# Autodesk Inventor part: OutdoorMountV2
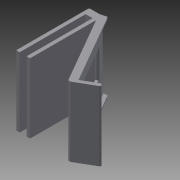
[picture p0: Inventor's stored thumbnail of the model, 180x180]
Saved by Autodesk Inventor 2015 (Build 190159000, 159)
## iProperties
Created: 2017-04
Part Number: OutdoorMountV2
Material: Generisch
Document SubType Name: Modeling
Designer: Andreas
Density: 1 g/cm^3
Appearance: Vorgabe
Author: Andreas
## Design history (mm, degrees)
sketch "Skizze1"
  geometry: L1 (0, 0)-(0, 105); L2 (0, 105)-(20, 105); L3 (0, 0)-(5, 0); L4 (5, 0)-(5, 95); L5 (5, 95)-(15, 95); L6 (15, 95)-(15, 0); L7 (15, 0)-(20, 0); L8 (20, 0)-(20, 95); L9 (25, 105)-(143.136, 105); L10 (20, 95)-(73.912, 1.622); L11 (20, 95)-(127.824, 95); L12 (20, 105)-(141.313, 105); L13 (20, 105)-(77.5, 5.407); L14 (20, 105)-(135, 105); L15 (77.5, 5.407)-(103.481, 20.407); L16 (103.481, 20.407)-(105.981, 16.077); L17 (105.981, 16.077)-(78.135, 0); L18 (78.135, 0)-(74.848, 0); L19 (74.848, 0)-(73.912, 1.622)
  constraints: 38 end point, 8 horizontal, 6 perpendicular, 2 equal length, 2 vertical, 1 parallel, 1 point on line
  dimensions: "d0" = 105 distance of L1.start L1.end; "d2" = 5 distance of L1.start L3.end; "d3" = 95 distance of L3.end L4.end; "d4" = 10 distance of L4.end L5.end; "d5" = 5 distance of L6.end L7.end; "d6" = 95 distance of L7.end L8.end; "d27" = 60 deg angle of L10 L11; "d35" = 20 distance of L1.end L2.end; "d69" = 115 distance of L2.end L13.end; "d70" = 60 deg angle of L13 L14; "d71" = 30 distance of L13.end L15.end; "d72" = 90 deg angle of L15 L13 (derived); "d75" = 5 distance of L15.end L16.end
extrude "Extrusion1" new body sketch "Skizze1" distance "d39" = 100; taper "d40" = 0 deg
sketch "Skizze3"
  geometry: L1 (20, 105)-(25, 105); L2 (20, 105)-(0, 105) reference; L3 (20, 105)-(77.5, 5.407); L4 (77.5, 5.407)-(20, 105) reference; L5 (77.5, 5.407)-(81.83, 7.907); L6 (103.481, 20.407)-(77.5, 5.407) reference; L7 (81.83, 7.907)-(24.33, 107.5); L8 (74.848, 0)-(20, 95) reference; L9 (81.83, 7.907)-(196.83, 7.907); L10 (24.33, 107.5)-(15, 105); 1 further point
  constraints: 12 end point, 2 horizontal, 2 point on line, 1 collinear, 1 equal length, 1 parallel
  dimensions: "d76" = 5 distance of L3.end L5.end; "d77" = 115 distance of L5.end L7.end; "d78" = 120 deg angle of L9 L7 (derived)
extrude "Extrusion3" join sketch "Skizze3" distance "d50" = 2.5; taper "d51" = 0 deg
sketch "Skizze4"
  geometry: L1 (-20, 105)-(-77.5, 5.407); L2 (-20, 105)-(-77.5, 5.407) reference; L3 (-77.5, 5.407)-(-81.83, 7.907); L4 (-77.5, 5.407)-(-81.83, 7.907) reference; L5 (-81.83, 7.907)-(-24.33, 107.5); L6 (-81.83, 7.907)-(-24.33, 107.5) reference; L7 (-20, 105)-(-77.5, 5.407) reference; L8 (-24.33, 107.5)-(-15, 105); L9 (-15, 105)-(-20, 105); L10 (0, 105)-(-20, 105) reference; 1 further point
  constraints: 10 end point, 4 collinear
fillet "Rundung3" dims "d57" = 2
sketch "Skizze5"
  geometry: L1 (27.5, 100)-(67.5, 100); L2 (67.5, 100)-(67.5, 20); L3 (67.5, 20)-(27.5, 20); L4 (27.5, 20)-(27.5, 100); 3 further points
  constraints: 8 end point, 2 parallel, 1 horizontal, 1 perpendicular
  dimensions: "d79" = 40 distance of L2.end L3.end; "d80" = 80 distance of L1.end L2.end
extrude "Extrusion5" cut sketch "Skizze5" distance "d81" = 5; taper "d82" = 0 deg
extrude "Extrusion6" join sketch "Skizze4" distance "d83" = 2.5; taper "d84" = 0 deg
fillet "Rundung10" dims "d85" = 2
fillet "Rundung11" dims "d86" = 2
node "Volumenkörper1"
